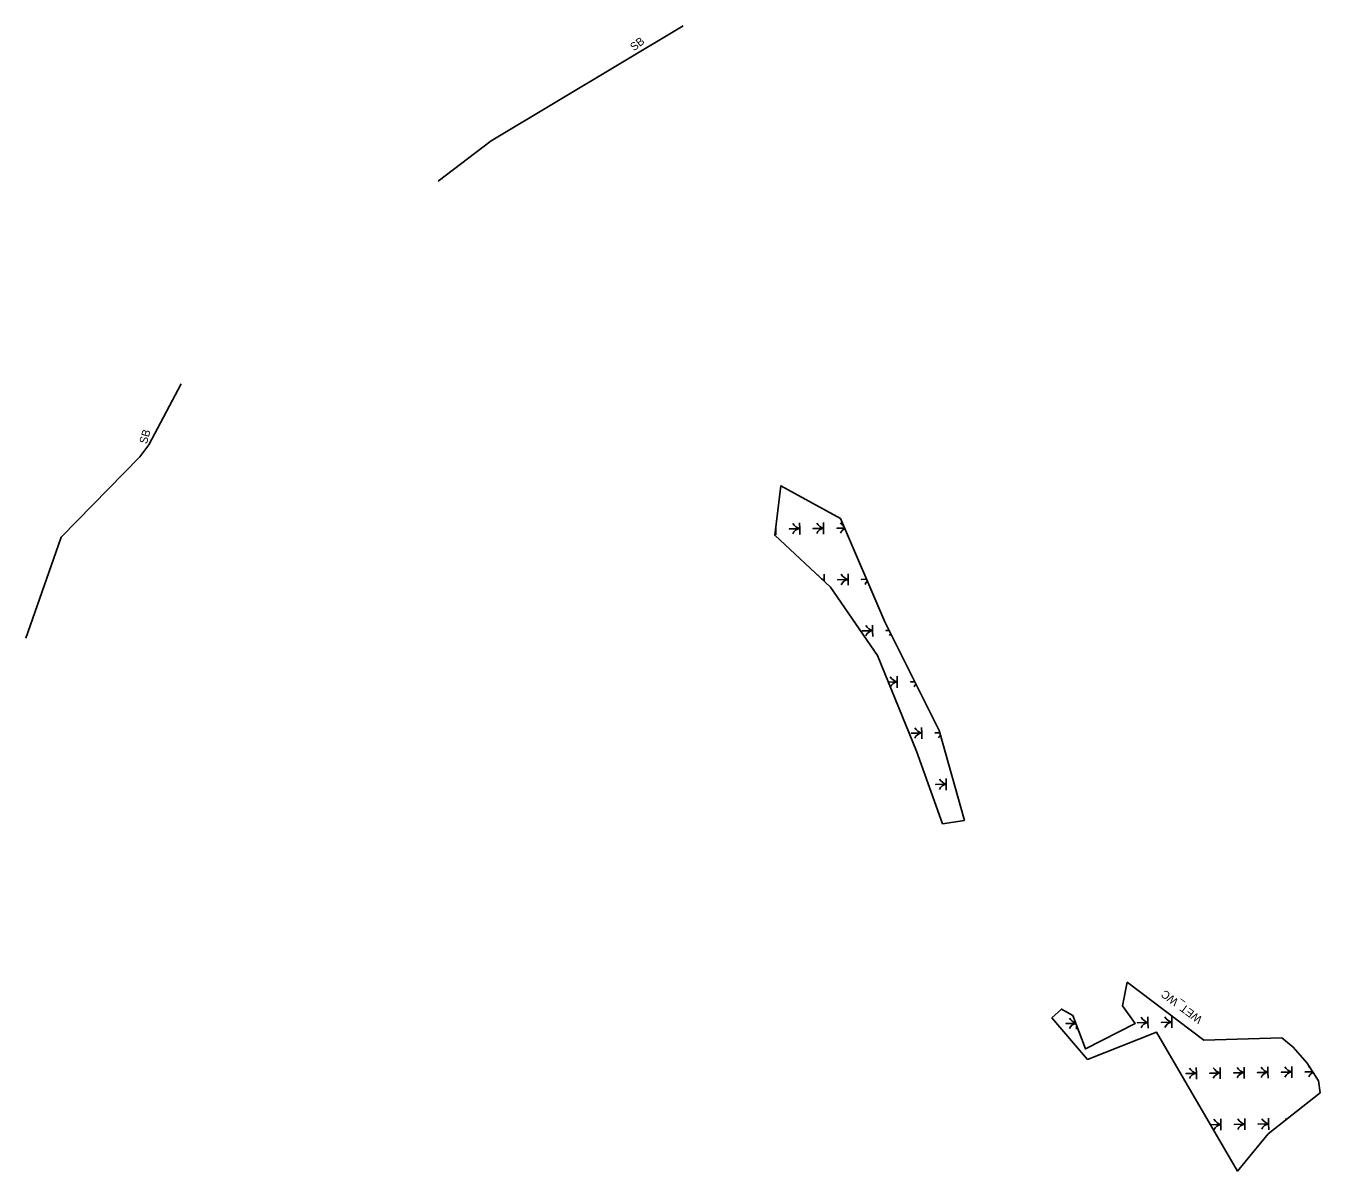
# Model space of a CAD drawing. Extents: x 1503676 to 1665494, y 654328 to 989038.
# Drawn here: x 1556457.7 to 1556942.9, y 690054.2 to 690483.5 of the extents above; entities that cross this region are included whole.
import ezdxf

# ---------------------------------------------------------------- set-up
doc = ezdxf.new("R2010")
doc.units = 0
for name, color, linetype in [('Level 16', 7, 'Continuous'), ('Level 26', 7, 'Continuous'), ('Level 3', 7, 'Continuous')]:
    doc.layers.add(name, color=color, linetype=linetype)

msp = doc.modelspace()

# ---------------------------------------------------------------- linework, layer by layer
at = {"layer": 'Level 16'}
for points in [[(1556612.23, 690425.29), (1556632.2, 690440.44), (1556704.11, 690483.47)], [(1556457.69, 690253.96), (1556468, 690283.54), (1556470.88, 690291.81), (1556500.47, 690321.99), (1556503.76, 690326.46), (1556515.9, 690349.26)]]:
    msp.add_lwpolyline(points, dxfattribs=at)
at = {"layer": 'Level 3'}
for p, q in [((1556842.6, 690111.48), (1556842.59, 690111.61)), ((1556851.6, 690107.42), (1556851.58, 690108.86)), ((1556941.29, 690089.3), (1556941.29, 690089.64))]:
    msp.add_line(p, q, dxfattribs=at)
for points in [[(1556809.66, 690185.65), (1556801.42, 690184.44), (1556791.56, 690211.66), (1556777, 690247.48), (1556759.41, 690273.14), (1556738.47, 690292.56), (1556740.75, 690311.1), (1556763.06, 690298.78), (1556779.77, 690260.11), (1556800.08, 690219.33)], [(1556923.47, 690068.2), (1556912.02, 690054.24), (1556881.59, 690106.33), (1556855.73, 690096.08), (1556842.41, 690111.71), (1556845.97, 690114.97), (1556850.17, 690112.57), (1556854.93, 690100.05), (1556873.62, 690109.59), (1556868.84, 690116.19), (1556870.62, 690125.04), (1556899.39, 690103.31), (1556928.56, 690104.18), (1556932.81, 690100.68), (1556938.05, 690094.75), (1556942.29, 690088.05), (1556942.94, 690083.59)]]:
    msp.add_lwpolyline(points, close=True, dxfattribs=at)
for points in [[(1556747.86, 690292.86), (1556747.83, 690295.01), (1556743.89, 690294.96), (1556747.83, 690295.01), (1556747.8, 690297.16)], [(1556756.8, 690292.98), (1556756.78, 690295.13), (1556752.83, 690295.08), (1556756.78, 690295.13), (1556756.75, 690297.28)], [(1556738.76, 690294.89), (1556738.89, 690294.9), (1556738.88, 690295.83)], [(1556738.92, 690292.74), (1556738.89, 690294.9), (1556738.76, 690294.89)], [(1556764.59, 690295.23), (1556761.78, 690295.2), (1556764.59, 690295.23)], [(1556756.52, 690275.82), (1556757.03, 690275.83), (1556757, 690277.98)], [(1556766, 690273.8), (1556765.97, 690275.95), (1556762.03, 690275.9), (1556765.97, 690275.95), (1556765.95, 690278.1)], [(1556757.04, 690275.35), (1556757.03, 690275.83), (1556756.52, 690275.82)], [(1556772.88, 690276.04), (1556770.97, 690276.01), (1556772.88, 690276.04)], [(1556775.2, 690254.62), (1556775.17, 690256.77), (1556771.23, 690256.71), (1556775.17, 690256.77), (1556775.14, 690258.92)], [(1556781.4, 690256.85), (1556780.17, 690256.83), (1556781.4, 690256.85)], [(1556781.04, 690237.54), (1556784.37, 690237.58), (1556784.34, 690239.73)], [(1556784.4, 690235.43), (1556784.37, 690237.58), (1556781.04, 690237.54)], [(1556790.95, 690237.67), (1556789.37, 690237.65), (1556790.95, 690237.67)], [(1556793.59, 690216.25), (1556793.57, 690218.4), (1556789.62, 690218.35), (1556793.57, 690218.4), (1556793.54, 690220.55)], [(1556800.32, 690218.49), (1556798.57, 690218.47), (1556800.32, 690218.49)], [(1556802.79, 690197.07), (1556802.76, 690199.22), (1556798.82, 690199.17), (1556802.76, 690199.22), (1556802.74, 690201.37)], [(1556851.31, 690109.57), (1556847.62, 690109.52), (1556851.31, 690109.57)], [(1556878.43, 690107.78), (1556878.4, 690109.93), (1556874.46, 690109.87), (1556878.4, 690109.93), (1556878.37, 690112.08)], [(1556887.37, 690107.89), (1556887.34, 690110.04), (1556883.4, 690109.99), (1556887.34, 690110.04), (1556887.32, 690112.19)], [(1556914.46, 690088.95), (1556914.43, 690091.1), (1556910.49, 690091.04), (1556914.43, 690091.1), (1556914.4, 690093.25)], [(1556923.4, 690089.06), (1556923.38, 690091.21), (1556919.43, 690091.16), (1556923.38, 690091.21), (1556923.35, 690093.36)], [(1556932.35, 690089.18), (1556932.32, 690091.33), (1556928.37, 690091.28), (1556932.32, 690091.33), (1556932.29, 690093.48)], [(1556896.57, 690088.71), (1556896.54, 690090.86), (1556892.6, 690090.81), (1556896.54, 690090.86), (1556896.51, 690093.01)], [(1556905.51, 690088.83), (1556905.49, 690090.98), (1556901.54, 690090.93), (1556905.49, 690090.98), (1556905.46, 690093.13)], [(1556940.15, 690091.43), (1556937.32, 690091.4), (1556940.15, 690091.43)], [(1556901.86, 690071.63), (1556905.74, 690071.68), (1556905.71, 690073.83)], [(1556914.71, 690069.65), (1556914.68, 690071.8), (1556910.74, 690071.74), (1556914.68, 690071.8), (1556914.66, 690073.95)], [(1556923.66, 690069.76), (1556923.63, 690071.91), (1556919.68, 690071.86), (1556923.63, 690071.91), (1556923.6, 690074.06)], [(1556905.77, 690069.53), (1556905.74, 690071.68), (1556901.86, 690071.63)]]:
    msp.add_lwpolyline(points, dxfattribs=at)
for centre, radius, start, end in [((1556749.29, 690299.59), 4.81, 212.8787, 252.3735), ((1556758.23, 690299.71), 4.81, 212.8787, 252.3735), ((1556767.18, 690299.83), 4.81, 212.8787, 232.4671), ((1556739.15, 690291.83), 3.07, 94.8916, 97.3018), ((1556740.34, 690299.48), 4.81, 250.8415, 252.3735), ((1556748.09, 690291.95), 3.07, 94.8916, 158.2863), ((1556757.04, 690292.07), 3.07, 94.8916, 158.2863), ((1556765.98, 690292.18), 3.07, 114.7105, 158.2863), ((1556758.48, 690280.41), 4.81, 212.8787, 215.0336), ((1556767.43, 690280.53), 4.81, 212.8787, 252.3735), ((1556758.48, 690280.41), 4.81, 239.2841, 252.3735), ((1556757.29, 690272.77), 3.07, 94.8916, 103.2045), ((1556766.24, 690272.88), 3.07, 94.8916, 158.2863), ((1556775.18, 690273), 3.07, 130.4404, 158.2863), ((1556776.63, 690261.35), 4.81, 212.8787, 252.3735), ((1556775.43, 690253.7), 3.07, 94.8916, 158.2863), ((1556784.38, 690253.82), 3.07, 141.8917, 158.2863), ((1556785.82, 690242.16), 4.81, 212.8787, 252.3735), ((1556784.63, 690234.52), 3.07, 94.8916, 157.4989), ((1556793.57, 690234.64), 3.07, 135.4576, 158.2863), ((1556795.02, 690222.98), 4.81, 212.8787, 252.3735), ((1556793.83, 690215.34), 3.07, 94.8916, 158.2863), ((1556802.77, 690215.46), 3.07, 135.6512, 158.2863), ((1556804.22, 690203.8), 4.81, 212.8787, 252.3735), ((1556803.03, 690196.16), 3.07, 94.8916, 158.2863), ((1556851.83, 690106.51), 3.07, 99.5587, 158.2863), ((1556853.02, 690114.15), 4.81, 212.8787, 248.5663), ((1556878.66, 690106.86), 3.07, 94.8916, 158.2863), ((1556879.86, 690114.51), 4.81, 212.8787, 252.3735), ((1556887.61, 690106.98), 3.07, 94.8916, 158.2863), ((1556888.8, 690114.62), 4.81, 212.8787, 252.3735), ((1556924.83, 690095.79), 4.81, 212.8787, 252.3735), ((1556933.78, 690095.91), 4.81, 212.8787, 252.3735), ((1556942.72, 690096.03), 4.81, 212.8787, 227.99), ((1556896.8, 690087.8), 3.07, 94.8916, 158.2863), ((1556898, 690095.44), 4.81, 212.8787, 252.3735), ((1556905.75, 690087.91), 3.07, 94.8916, 158.2863), ((1556906.94, 690095.56), 4.81, 212.8787, 252.3735), ((1556914.69, 690088.03), 3.07, 94.8916, 158.2863), ((1556915.89, 690095.68), 4.81, 212.8787, 252.3735), ((1556923.64, 690088.15), 3.07, 94.8916, 158.2863), ((1556932.58, 690088.27), 3.07, 94.8916, 158.2863), ((1556941.53, 690088.38), 3.07, 113.5492, 158.2863), ((1556916.14, 690076.38), 4.81, 212.8787, 252.3735), ((1556925.08, 690076.49), 4.81, 212.8787, 252.3735), ((1556934.03, 690076.61), 4.81, 212.8787, 218.9177), ((1556906, 690068.62), 3.07, 94.8916, 158.2863), ((1556907.19, 690076.26), 4.81, 212.8787, 252.3735), ((1556914.95, 690068.73), 3.07, 94.8916, 158.2863), ((1556923.89, 690068.85), 3.07, 94.8916, 158.2863)]:
    msp.add_arc(centre, radius, start, end, dxfattribs=at)

# ---------------------------------------------------------------- texts
at = {"layer": 'Level 26'}
for s, rotation, p in [('SB', 37.6844, (1556685.68, 690473.9)), ('SB', 74.1712, (1556503.02, 690326.56)), ('WET_WC', 143.3321, (1556899.06, 690111.68))]:
    msp.add_text(s, height=3, rotation=rotation, dxfattribs=at).set_placement(p)

doc.saveas('drawing.dxf')
